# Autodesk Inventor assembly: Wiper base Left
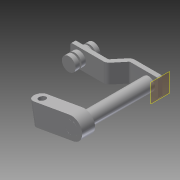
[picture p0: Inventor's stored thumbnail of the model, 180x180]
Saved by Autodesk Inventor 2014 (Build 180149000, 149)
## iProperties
Created: 2006-03
Part Number: Wiper base Left
Document SubType Name: Assembly
Designer: Autodesk, Inc.
Mass: 378.494 g
Surface Area: 188.994 cm^2
Volume: 48.8379 cm^3
Density: 7.75 g/cm^3
Author: Autodesk, Inc.
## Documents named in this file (5)
- C:\Users\iTools\Desktop\tutorial files\Dynamic Simulation 4\Components\Wiper base Left.iam
- C:\Users\iTools\Desktop\tutorial files\Dynamic Simulation 4\Components\Axis_Left.ipt
- C:\Users\iTools\Desktop\tutorial files\Dynamic Simulation 4\Components\Crank_left.ipt
- C:\Users\iTools\Desktop\tutorial files\Dynamic Simulation 4\Components\Wiper Support.ipt
- C:\Users\iTools\Desktop\tutorial files\Dynamic Simulation 4\Components\Pawn.ipt
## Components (5 placed, 4 different names)
1. Crank_left:1 — Mate:31, Mate:32, Mate:33, Mate:34, Mate:35, Mate:36, Insert:1
2. Axis_Left:1 — Mate:17, Flush:3, Angle:8, Mate:34, Mate:35, Mate:36
3. Wiper Support:1 — Mate:17, Flush:3, Angle:8
4. Pawn:2 — Insert:1, Insert:2
5. Pawn:1 — Insert:2
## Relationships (11: Mate 7, Insert 2, Flush 1, Angle 1)
- Mate:17: Axis_Left:1 ↔ Wiper Support:1
- Flush:3: Axis_Left:1 ↔ Wiper Support:1
- Angle:8: Axis_Left:1 ↔ Wiper Support:1
- Mate:31: Crank_left:1
- Mate:32: Crank_left:1
- Mate:33: Crank_left:1
- Mate:34: Crank_left:1 ↔ Axis_Left:1
- Mate:35: Crank_left:1 ↔ Axis_Left:1
- Mate:36: Crank_left:1 ↔ Axis_Left:1
- Insert:1: Crank_left:1 ↔ Pawn:2
- Insert:2: Pawn:2 ↔ Pawn:1
